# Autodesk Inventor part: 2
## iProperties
Created: 2012-03
Part Number: 2
Document SubType Name: Modeling
Designer: Administrator
Density: 7.85 g/cm^3
Material: Steel
Mass: 102.516 g
Surface Area: 109.284 cm^2
Volume: 13.0594 cm^3
Translation Standard: STEP AP203
FileName: //expscmdclustefs.cadenas.external/client_exchange/iodir/jobs/output/wkb42693463_no0/STEP/229_9001_2_03.stp
PostProcessor: Build: 236a, Release: 2009 RTM - Date: Fri 02/22/2008
Sent Units: CM
Uncertainty: 0.0
Author: Administrator
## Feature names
1. Base1
